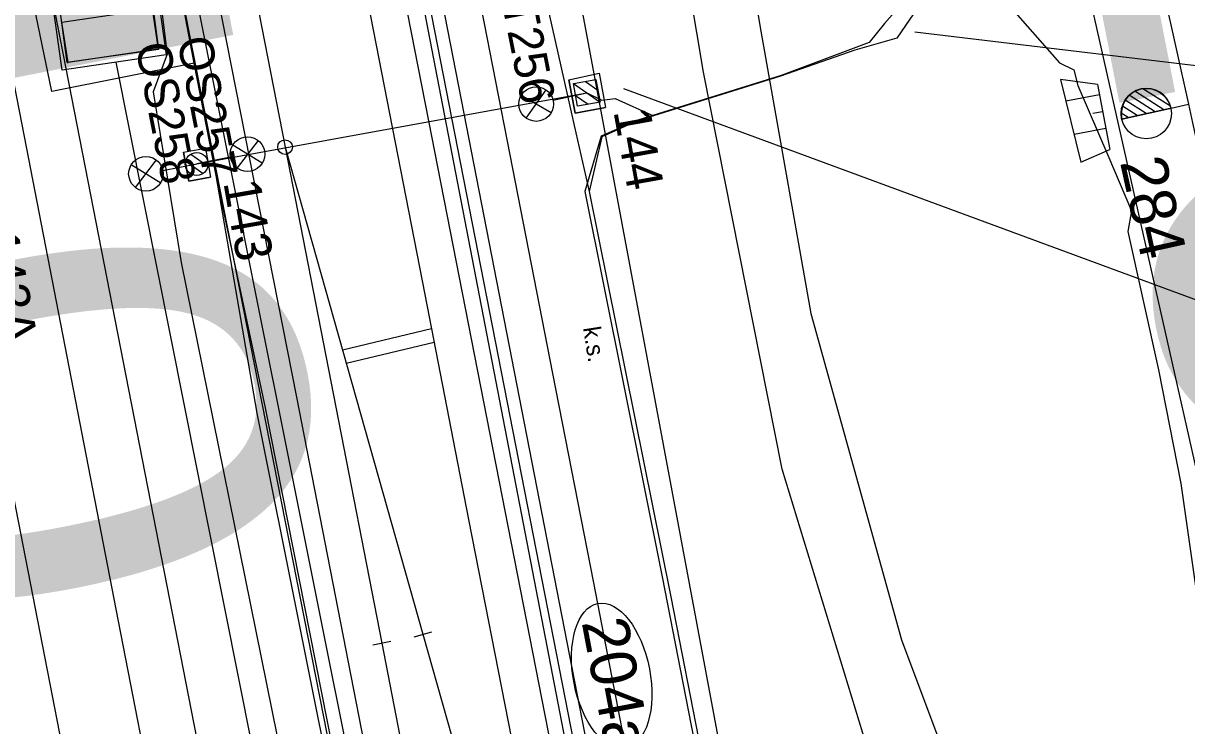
# Model space of a CAD drawing. Extents: x -545846 to -545044, y -1122650 to -1119108.
# Drawn here: x -545709.7 to -545659, y -1119324.5 to -1119293.9 of the extents above; entities that cross this region are included whole.
import ezdxf

# ---------------------------------------------------------------- set-up
doc = ezdxf.new("R2010")
doc.units = 0
for name, color, linetype in [('osvětlené plochy-hodnota-obrys', 7, 'Continuous'), ('Vrstva 1', 7, 'Continuous'), ('Vrstva 1 - Koleje', 7, 'Continuous'), ('Vrstva 11', 7, 'Continuous'), ('Vrstva 11 - Trakce', 7, 'Continuous'), ('Vrstva 12 - Trakce zaklady', 7, 'Continuous'), ('Vrstva 13', 7, 'Continuous'), ('Vrstva 2', 7, 'Continuous'), ('Vrstva 2 - Vyhybky', 7, 'Continuous'), ('Vrstva 25', 7, 'Continuous'), ('Vrstva 26', 7, 'Continuous'), ('Vrstva 31', 7, 'Continuous'), ('Vrstva 33 - prvky sdelzar', 7, 'Continuous'), ('Vrstva 4 - Teren - stezky - prechody - plochy', 7, 'Continuous'), ('Vrstva 44', 7, 'Continuous'), ('Vrstva 48', 7, 'Continuous'), ('Vrstva 49', 7, 'Continuous'), ('Vrstva 63', 7, 'Continuous'), ('Vrstva 7 - Namezniky-vystroj', 7, 'Continuous')]:
    doc.layers.add(name, color=color, linetype=linetype)

msp = doc.modelspace()

# ---------------------------------------------------------------- linework, layer by layer
at = {"layer": 'osvětlené plochy-hodnota-obrys'}
for points in [[(-545700.341, -1119250.428), (-545705.955, -1119221.665), (-545699.039, -1119220.315), (-545660.607, -1119425.918), (-545653.752, -1119372.856), (-545653.095, -1119348.321), (-545657.119, -1119319.988), (-545685.945, -1119192.198), (-545694.33, -1119168.5)], [(-545664.282, -1119515.639), (-545680.447, -1119467.233), (-545736.202, -1119180.74), (-545730.573, -1119179.645)], [(-545730.573, -1119179.645), (-545675.345, -1119462.605), (-545660.82, -1119505.941)], [(-545716.386, -1119223.717), (-545705.994, -1119221.66), (-545669.439, -1119408.759), (-545659.4, -1119462.635), (-545647.69, -1119521.347), (-545640.519, -1119558.729), (-545633.585, -1119589.698), (-545629.517, -1119613.814), (-545623.042, -1119645.057), (-545619.034, -1119667.556), (-545607.519, -1119727.517)], [(-545610.895, -1119760.665), (-545622.836, -1119699.488), (-545637.26, -1119626.872), (-545653.542, -1119543.449), (-545716.386, -1119223.717)]]:
    msp.add_lwpolyline(points, dxfattribs=at)
at = {"layer": 'Vrstva 1'}
for points in [[(-545684.737, -1119182.215), (-545681.048, -1119198.017), (-545679.115, -1119206.463), (-545675.534, -1119222.463), (-545673.245, -1119232.849), (-545669.06, -1119251.885), (-545668.909, -1119252.525), (-545665.698, -1119267.062), (-545662.183, -1119282.93), (-545658.971, -1119297.417), (-545658.784, -1119298.22), (-545656.764, -1119307.375), (-545653.043, -1119323.451), (-545653.043, -1119323.451)], [(-545720.48, -1119243.554), (-545716.211, -1119265.458), (-545709.71, -1119298.83), (-545705.603, -1119319.946), (-545703.826, -1119329.138), (-545700.44, -1119346.499), (-545698.393, -1119357.038), (-545695.828, -1119370.213), (-545691.674, -1119391.619), (-545690.242, -1119398.846), (-545690.242, -1119398.846)]]:
    msp.add_lwpolyline(points, dxfattribs=at)
at = {"layer": 'Vrstva 1 - Koleje'}
for points in [[(-545709.729, -1119216.005), (-545707.216, -1119228.928), (-545705.339, -1119238.544), (-545703.194, -1119249.533), (-545701.169, -1119259.932), (-545699.297, -1119269.549), (-545697.971, -1119276.345), (-545697.744, -1119277.51), (-545696.05, -1119286.199), (-545694.131, -1119296.035), (-545692.248, -1119305.709), (-545690.337, -1119315.525), (-545688.473, -1119325.085), (-545686.978, -1119332.737), (-545682.769, -1119354.327), (-545679.71, -1119370.018), (-545678.941, -1119373.959), (-545678.788, -1119374.744)], [(-545703.92, -1119220.722), (-545702.554, -1119227.966), (-545700.678, -1119237.615), (-545696.679, -1119258.063), (-545694.657, -1119268.387), (-545692.353, -1119280.184), (-545690.421, -1119290.021), (-545688.542, -1119299.62), (-545686.677, -1119309.149), (-545684.899, -1119318.277), (-545683.134, -1119327.367), (-545681.637, -1119335.101), (-545671.298, -1119388.278)], [(-545702.32, -1119278.874), (-545702.167, -1119279.659), (-545698.336, -1119299.285), (-545692.327, -1119320.523), (-545688.744, -1119333.21), (-545682.769, -1119354.327), (-545678.941, -1119373.959), (-545678.788, -1119374.744)], [(-545702.32, -1119278.874), (-545702.167, -1119279.659), (-545701.383, -1119283.673), (-545698.336, -1119299.285), (-545694.116, -1119320.907), (-545692.368, -1119329.917), (-545690.438, -1119339.83), (-545688.573, -1119349.383), (-545687.302, -1119355.899), (-545685.328, -1119366.028), (-545683.274, -1119376.56), (-545681.242, -1119386.97)]]:
    msp.add_lwpolyline(points, dxfattribs=at)
msp.add_ellipse((-545684.1, -1119322.337), major_axis=(0.602, -3.154), ratio=0.521067, dxfattribs=at)
at = {"layer": 'Vrstva 11'}
for points in [[(-545660.442, -1119392.092), (-545661.65, -1119360.917), (-545664.424, -1119348.304), (-545668.265, -1119337.271), (-545672.842, -1119325.88), (-545676.672, -1119313.329), (-545680.107, -1119296.016), (-545683.357, -1119276.628), (-545687.705, -1119260.217), (-545691.925, -1119249.152), (-545696.51, -1119233.839), (-545699.129, -1119217.635), (-545699.471, -1119201.94)], [(-545696.533, -1119202.507), (-545696.456, -1119218.879), (-545693.686, -1119234.563), (-545688.691, -1119250.208), (-545683.376, -1119265.642), (-545680.716, -1119275.8), (-545677.596, -1119294.23), (-545675.42, -1119306.545), (-545671.472, -1119320.767), (-545664.905, -1119338.296), (-545660.65, -1119351.238), (-545658.49, -1119363.866), (-545658.1, -1119379.253), (-545657.366, -1119395.247), (-545656.18, -1119402.951), (-545654.767, -1119406.288)]]:
    msp.add_lwpolyline(points, dxfattribs=at)
at = {"layer": 'Vrstva 11 - Trakce'}
for p, q in [((-545685.246, -1119296.421), (-545684.704, -1119296.798)), ((-545702.185, -1119300.018), (-545685.19, -1119296.919)), ((-545685.768, -1119296.515), (-545684.61, -1119297.319)), ((-545685.677, -1119297.034), (-545685.128, -1119297.416)), ((-545702.667, -1119299.898), (-545701.909, -1119300.431)), ((-545702.446, -1119299.596), (-545701.698, -1119300.121))]:
    msp.add_line(p, q, dxfattribs=at)
msp.add_lwpolyline([(-545684.787, -1119296.338), (-545684.609, -1119297.322), (-545685.593, -1119297.5), (-545685.771, -1119296.516)], close=True, dxfattribs=at)
msp.add_circle((-545702.185, -1119300.018), 0.5, dxfattribs=at)
at = {"layer": 'Vrstva 12 - Trakce zaklady'}
for p, q in [((-545684.647, -1119296.062), (-545684.378, -1119297.553)), ((-545702.758, -1119299.504), (-545701.808, -1119299.33)), ((-545702.524, -1119300.766), (-545701.587, -1119300.592))]:
    msp.add_line(p, q, dxfattribs=at)
for points in [[(-545685.695, -1119297.812), (-545685.962, -1119296.347), (-545684.647, -1119296.062), (-545684.378, -1119297.553), (-545685.695, -1119297.812)], [(-545685.962, -1119296.347), (-545685.962, -1119296.347), (-545684.647, -1119296.062), (-545684.647, -1119296.062)], [(-545685.962, -1119296.347), (-545685.962, -1119296.347), (-545685.695, -1119297.812), (-545685.695, -1119297.812)], [(-545685.695, -1119297.812), (-545684.378, -1119297.553), (-545684.378, -1119297.553)], [(-545701.808, -1119299.33), (-545701.587, -1119300.592), (-545702.524, -1119300.766), (-545702.758, -1119299.504), (-545701.808, -1119299.33)], [(-545702.758, -1119299.504), (-545702.758, -1119299.504), (-545702.524, -1119300.766), (-545702.524, -1119300.766)], [(-545701.808, -1119299.33), (-545701.808, -1119299.33), (-545701.587, -1119300.592), (-545701.587, -1119300.592)]]:
    msp.add_lwpolyline(points, dxfattribs=at)
at = {"layer": 'Vrstva 13'}
for p, q in [((-545703.854, -1119295.031), (-545703.863, -1119295.02)), ((-545707.829, -1119295.603), (-545707.788, -1119295.597))]:
    msp.add_line(p, q, dxfattribs=at)
for points in [[(-545703.51, -1119295.266), (-545708.056, -1119295.928), (-545708.608, -1119291.988), (-545704.07, -1119291.308)], [(-545708.279, -1119292.226), (-545704.301, -1119291.644), (-545703.854, -1119295.031), (-545707.829, -1119295.603)], [(-545708.058, -1119293.833), (-545704.12, -1119293.252), (-545703.863, -1119295.02), (-545707.788, -1119295.597)]]:
    msp.add_lwpolyline(points, close=True, dxfattribs=at)
at = {"layer": 'Vrstva 2'}
for p, q in [((-545660.035, -1119297.655), (-545661.299, -1119296.85)), ((-545659.748, -1119297.505), (-545660.949, -1119296.739)), ((-545660.812, -1119297.827), (-545661.726, -1119297.245)), ((-545660.423, -1119297.741), (-545661.547, -1119297.026)), ((-545659.723, -1119297.586), (-545658.971, -1119297.417)), ((-545661.589, -1119297.999), (-545661.891, -1119297.807)), ((-545659.724, -1119297.586), (-545661.867, -1119298.061)), ((-545661.867, -1119298.061), (-545659.724, -1119297.586)), ((-545661.2, -1119297.913), (-545661.843, -1119297.504)), ((-545659.724, -1119297.586), (-545659.724, -1119297.586))]:
    msp.add_line(p, q, dxfattribs=at)
msp.add_circle((-545660.802, -1119297.824), 1.097, dxfattribs=at)
msp.add_arc((-545660.796, -1119297.823), 1.098, 12.5207, 192.4816, dxfattribs=at)
at = {"layer": 'Vrstva 2 - Vyhybky'}
for p, q in [((-545692.712, -1119320.632), (-545691.942, -1119320.414)), ((-545694.509, -1119320.983), (-545693.723, -1119320.831))]:
    msp.add_line(p, q, dxfattribs=at)
for points in [[(-545702.32, -1119278.874), (-545702.167, -1119279.659), (-545698.336, -1119299.285), (-545694.116, -1119320.907)], [(-545698.336, -1119299.285), (-545692.327, -1119320.523)]]:
    msp.add_lwpolyline(points, dxfattribs=at)
msp.add_circle((-545698.336, -1119299.285), 0.32, dxfattribs=at)
at = {"layer": 'Vrstva 25'}
for p, q in [((-545687.833, -1119298.018), (-545686.953, -1119296.794)), ((-545686.654, -1119297.246), (-545685.19, -1119296.919)), ((-545688.039, -1119297.023), (-545686.734, -1119297.78)), ((-545699.513, -1119298.991), (-545700.426, -1119300.19)), ((-545699.334, -1119299.99), (-545700.618, -1119299.199)), ((-545704.857, -1119301.044), (-545703.944, -1119299.845)), ((-545703.657, -1119300.305), (-545702.185, -1119300.018)), ((-545700.713, -1119299.731), (-545702.185, -1119300.018)), ((-545705.036, -1119300.045), (-545703.752, -1119300.837))]:
    msp.add_line(p, q, dxfattribs=at)
msp.add_lwpolyline([(-545702.185, -1119300.018), (-545685.19, -1119296.919)], dxfattribs=at)
for centre in [(-545687.39, -1119297.408), (-545699.972, -1119299.589), (-545704.398, -1119300.447)]:
    msp.add_circle(centre, 0.754, dxfattribs=at)
at = {"layer": 'Vrstva 26'}
for points in [[(-545723.4, -1119198.98), (-545720.917, -1119199.104), (-545717.951, -1119198.296), (-545714.968, -1119197.483), (-545713.419, -1119197.11), (-545709.47, -1119196.16), (-545706.908, -1119198.458), (-545704.395, -1119207.525), (-545703.903, -1119209.931), (-545701.434, -1119221.82), (-545699.39, -1119231.84), (-545698.841, -1119235.301), (-545696.486, -1119245.259), (-545690.376, -1119277.628), (-545689.223, -1119281.311), (-545688.887, -1119282.369), (-545687.72, -1119289.475), (-545685.667, -1119298.667), (-545685.076, -1119301.217)], [(-545669.284, -1119291.014), (-545671.67, -1119294.536), (-545673.507, -1119295.057), (-545676.739, -1119296.191), (-545682.284, -1119297.916), (-545682.944, -1119298.121), (-545684.526, -1119298.831), (-545685.076, -1119301.217), (-545681.518, -1119318.897), (-545678.885, -1119332.432), (-545675.639, -1119348.357), (-545675.262, -1119352.744), (-545674.052, -1119356.623), (-545671.95, -1119367.037), (-545671.035, -1119371.566), (-545669.914, -1119375.777), (-545669.221, -1119379.711), (-545666.658, -1119394.257), (-545666.038, -1119395.572), (-545665.51, -1119396.73), (-545664.32, -1119397.6), (-545664.49, -1119398.35), (-545664.917, -1119398.423)], [(-545671.67, -1119294.536), (-545673.507, -1119295.057), (-545676.739, -1119296.191), (-545682.284, -1119297.916), (-545682.944, -1119298.121), (-545684.526, -1119298.831)], [(-545685.19, -1119296.919), (-545684.53, -1119297.24), (-545683.95, -1119297.16), (-545682.284, -1119297.916)]]:
    msp.add_lwpolyline(points, dxfattribs=at)
at = {"layer": 'Vrstva 31'}
for points in [[(-545705.72, -1119289.965), (-545705.666, -1119289.946), (-545703.957, -1119291.398), (-545703.473, -1119295.232), (-545704.09, -1119296.872), (-545702.861, -1119304.32), (-545698.681, -1119324.981), (-545696.502, -1119336.531), (-545693.744, -1119351.629), (-545691.156, -1119365.479), (-545687.442, -1119383.663), (-545686.29, -1119382.94)], [(-545669.783, -1119291.131), (-545672.206, -1119293.898), (-545672.878, -1119294.726), (-545676.721, -1119296.165), (-545682.968, -1119298.105), (-545684.562, -1119298.802), (-545685.271, -1119301.217), (-545681.902, -1119318.023), (-545679.037, -1119332.697), (-545675.878, -1119348.362), (-545675.455, -1119352.785), (-545674.365, -1119356.614), (-545673.497, -1119359.701), (-545672.189, -1119367.114), (-545671.293, -1119371.554), (-545670.112, -1119375.778), (-545669.417, -1119379.549), (-545670.73, -1119380.04), (-545672.065, -1119380.44), (-545673.516, -1119380.759), (-545675.08, -1119380.973)], [(-545669.284, -1119291.014), (-545671.67, -1119294.536), (-545673.507, -1119295.057), (-545676.739, -1119296.191), (-545682.284, -1119297.916), (-545682.944, -1119298.121), (-545684.526, -1119298.831), (-545685.076, -1119301.217), (-545681.518, -1119318.897), (-545678.885, -1119332.432), (-545675.639, -1119348.357), (-545675.262, -1119352.744), (-545674.052, -1119356.623), (-545671.035, -1119371.566), (-545669.914, -1119375.777)], [(-545668.954, -1119291.079), (-545667.698, -1119292.072), (-545664.584, -1119295.604), (-545663.967, -1119295.916), (-545663.78, -1119296.605), (-545662.476, -1119299.636), (-545661.444, -1119302.068), (-545661.613, -1119302.97), (-545660.277, -1119308.997), (-545659.299, -1119313.957), (-545658.018, -1119322.913), (-545656.576, -1119330.571), (-545655.591, -1119333.102), (-545654.529, -1119340.855), (-545654.159, -1119343.74), (-545652.607, -1119354.843), (-545652.828, -1119356.763), (-545652.968, -1119360.395), (-545653.389, -1119368.277), (-545654.002, -1119377.884), (-545653.796, -1119384.348)]]:
    msp.add_lwpolyline(points, dxfattribs=at)
at = {"layer": 'Vrstva 33 - prvky sdelzar'}
msp.add_lwpolyline([(-545671.67, -1119294.536), (-545673.507, -1119295.057), (-545676.739, -1119296.191), (-545682.284, -1119297.916), (-545682.944, -1119298.121), (-545684.526, -1119298.831)], dxfattribs=at)
at = {"layer": 'Vrstva 4 - Teren - stezky - prechody - plochy'}
for points in [[(-545704.229, -1119285.397), (-545702.296, -1119295.62), (-545708.495, -1119296.855), (-545710.805, -1119285.764), (-545709.428, -1119284.376), (-545706.362, -1119283.922), (-545704.229, -1119285.397), (-545706.803, -1119274.001), (-545706.075, -1119273.312), (-545711.091, -1119248.834), (-545711.901, -1119243.963), (-545720.224, -1119201.665), (-545721.285, -1119195.757), (-545731.313, -1119142.94)], [(-545706.355, -1119218.803), (-545707.51, -1119218.932), (-545702.452, -1119245.262), (-545692.085, -1119298.133), (-545681.28, -1119353.378), (-545672.8, -1119397.126), (-545671.145, -1119404.595), (-545668.049, -1119418.039), (-545667.069, -1119417.83)], [(-545706.355, -1119218.803), (-545705.856, -1119218.828), (-545700.854, -1119244.947), (-545690.54, -1119297.817), (-545679.814, -1119352.936), (-545671.301, -1119396.597), (-545667.069, -1119417.83)], [(-545663.732, -1119493.482), (-545662.217, -1119493.136), (-545662.27, -1119492.38), (-545664.76, -1119479.724), (-545673.059, -1119437.391), (-545683.638, -1119382.878), (-545688.896, -1119355.974), (-545694.44, -1119327.554), (-545697.827, -1119310.185), (-545704.93, -1119274.138), (-545706.059, -1119274.463)], [(-545663.732, -1119493.482), (-545663.86, -1119492.962), (-545666.439, -1119479.174), (-545674.481, -1119437.861), (-545674.838, -1119435.68), (-545679.752, -1119410.669), (-545685.159, -1119383.219), (-545690.428, -1119356.383), (-545695.755, -1119327.999), (-545699.195, -1119310.645), (-545701.333, -1119300.523), (-545702.296, -1119295.62), (-545704.229, -1119285.397), (-545706.059, -1119274.463)], [(-545674.838, -1119435.68), (-545676.549, -1119430.017), (-545679.882, -1119411.316), (-545685.521, -1119383.317), (-545690.583, -1119356.379), (-545695.903, -1119329.098), (-545699.555, -1119310.884), (-545701.333, -1119300.523)], [(-545674.838, -1119435.68), (-545679.752, -1119410.669), (-545685.159, -1119383.219), (-545690.428, -1119356.383), (-545695.755, -1119327.999), (-545699.195, -1119310.645), (-545701.333, -1119300.523)]]:
    msp.add_lwpolyline(points, dxfattribs=at)
at = {"layer": 'Vrstva 44'}
for points in [[(-545696.014, -1119273.956), (-545685.646, -1119327.665), (-545676.105, -1119375.826), (-545685.431, -1119377.392), (-545685.693, -1119377.451)], [(-545705.625, -1119275.692), (-545694.817, -1119329.698), (-545685.765, -1119377.133), (-545685.693, -1119377.451)], [(-545705.713, -1119295.587), (-545698.586, -1119331.363), (-545698.458, -1119331.735), (-545698.387, -1119332.167), (-545688.892, -1119380.643)]]:
    msp.add_lwpolyline(points, dxfattribs=at)
at = {"layer": 'Vrstva 48'}
for p, q in [((-545662.847, -1119297.006), (-545664.306, -1119297.282)), ((-545662.707, -1119297.743), (-545663.134, -1119297.823)), ((-545662.568, -1119298.48), (-545663.95, -1119298.741))]:
    msp.add_line(p, q, dxfattribs=at)
at = {"layer": 'Vrstva 49'}
msp.add_line((-545662.933, -1119296.549), (-545662.396, -1119299.392), dxfattribs=at)
msp.add_lwpolyline([(-545662.933, -1119296.549), (-545664.536, -1119296.337), (-545663.658, -1119299.938), (-545662.396, -1119299.392)], dxfattribs=at)
at = {"layer": 'Vrstva 63'}
for p, q in [((-545582.868, -1119304.869), (-545670.886, -1119294.271)), ((-545576.744, -1119336.162), (-545683.579, -1119296.748))]:
    msp.add_line(p, q, dxfattribs=at)
at = {"layer": 'Vrstva 7 - Namezniky-vystroj'}
for p, q in [((-545695.836, -1119308.122), (-545691.958, -1119307.198)), ((-545695.672, -1119308.7), (-545691.843, -1119307.788))]:
    msp.add_line(p, q, dxfattribs=at)

# ---------------------------------------------------------------- texts
at = {"layer": 'osvětlené plochy-hodnota-obrys'}
for p in [(-545664.947, -1119282.192), (-545724.941, -1119288.618)]:
    msp.add_text('10', height=22.7812, rotation=281.0956, dxfattribs=at).set_placement(p)
at = {"layer": 'Vrstva 1 - Koleje'}
msp.add_text('204a', height=2, rotation=280.685, dxfattribs=at).set_placement((-545685.414, -1119319.989))
at = {"layer": 'Vrstva 11 - Trakce'}
for s, rotation, p in [('144', 280.227, (-545684.028, -1119297.726)), ('143', 279.9329, (-545701.027, -1119300.831)), ('143A', 280.3685, (-545711.569, -1119303.06))]:
    msp.add_text(s, height=1.6, rotation=rotation, dxfattribs=at).set_placement(p)
at = {"layer": 'Vrstva 2'}
msp.add_text('284', height=2, rotation=282.5012, dxfattribs=at).set_placement((-545661.956, -1119299.93))
at = {"layer": 'Vrstva 25'}
for s, rotation, p in [('OT256', 281.0756, (-545689.189, -1119291.476)), ('OS258', 281.0453, (-545704.863, -1119294.865)), ('OS257', 281.0453, (-545703.047, -1119294.603))]:
    msp.add_text(s, height=1.5, rotation=rotation, dxfattribs=at).set_placement(p)
at = {"layer": 'Vrstva 63'}
msp.add_text('k.s.', height=0.75, rotation=278.866, dxfattribs=at).set_placement((-545685.351, -1119307.164))

doc.saveas('drawing.dxf')
